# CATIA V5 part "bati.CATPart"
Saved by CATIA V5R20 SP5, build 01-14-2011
Part number: bati
Publications: "longueur bati", "epaisseur", "rayontrou"
Bounding box of the stored display mesh (mm): x -125 to 0, y 0 to 2100.481, z 0 to 1204.58
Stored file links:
  F:\iao fini\bati.CATPart
  F:\iao fini\iao-finipbgliss.CATProduct
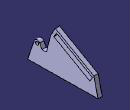
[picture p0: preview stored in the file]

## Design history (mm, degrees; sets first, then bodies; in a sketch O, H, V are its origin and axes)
Parameters
  `longueur bati` = 1 mm
  epaisseur = 125 mm
  rayontrou = 50 mm
Set1
  Plane1 "plan profil": linked copy from another document
  Point1: linked copy from another document
  Line1: linked copy from another document
  Point2: linked copy from another document
Body1 (main body)
  Sketch1 on Plane1, origin (0, 0, 0), H (0, 1, 0), V (0, 0, 1)
    line L1 (681.9123, 951.1125) -> (557.3138, 463.899)
    line L2 (681.9123, 951.1125) -> (825.4943, 1204.5798)
    line L3 (825.4943, 1204.5798) -> (1975.5785, 553.09)
    line L4 (1975.5785, 553.09) -> (2100.4814, 29.6002)
    line L5 (2100.4814, 29.6002) -> (0, 0)
    line L6 (557.3138, 463.899) -> (426.1909, 462.0512)
    arc A1 centre (280, 550) radius 90 from (360.0975, 591.0413) to (194.6984, 578.699) ccw
    point P7 (280, 550)
    reference projected point E1 (280, 550) from Point1
    line L7 (0, 0) -> (194.6984, 578.699)
    point P8 (0, 0)
    line L8 (360.0975, 591.0413) -> (426.1909, 462.0512)
    reference projected line E2 (2799.5367, -86.0537) -> (25.6737, 1485.2604) from Line1
    line L9 (856.3954, 1100.8777) -> (782.4628, 970.3635)
    line L10 (782.4628, 970.3635) -> (1857.0302, 361.6518)
    line L11 (1857.0302, 361.6518) -> (1930.9628, 492.1661)
    line L12 (1930.9628, 492.1661) -> (856.3954, 1100.8777)
    reference projected line E3 (2799.5367, -86.0537) -> (25.6737, 1485.2604) from Line1
    reference projected point E4 (280, 550) from Point1
    reference projected line E5 (2799.5367, -86.0537) -> (25.6737, 1485.2604) from Line1
    reference projected line E6 (2799.5367, -86.0537) -> (25.6737, 1485.2604) from Line1
    reference projected point E7 (280, 550) from Point1
    reference projected point E8 (280, 550) from Point1
    reference projected point E9 (280, 550) from Point1
    reference projected point E10 (280, 550) from Point1
    reference projected line E11 (2799.5367, -86.0537) -> (25.6737, 1485.2604) from Line1
    reference projected line E12 (2799.5367, -86.0537) -> (25.6737, 1485.2604) from Line1
    reference projected line E13 (2799.5367, -86.0537) -> (25.6737, 1485.2604) from Line1
    distance A1 E4 = 90 {= `longueur bati` *90}
    distance E5 L3 = 150 {= `longueur bati` *150}
    distance E6 L12 = 75 {= `longueur bati` *75}
    distance L9 E7 = 230 {= `longueur bati` *230}
    distance L11 L9 = 1235 {= `longueur bati` *1235}
    distance E8 L2 = 152 {= `longueur bati` *152}
    distance L6 L5 = 456 {= `longueur bati` *456}
    distance L8 O = 590 {= `longueur bati` *590}
    distance L4 O = 2050 {= `longueur bati` *2050}
    distance E9 L4 = 1650 {= `longueur bati` *1650}
    distance E10 L1 = 290 {= `longueur bati` *290}
    distance O L1 = 425 {= `longueur bati` *425}
    tangency: A1 L6, L7 A1, L8 A1
    coincidence: P7 E1, P8 L5, P8 H, O P8
    perpendicularity: L2 L3, L10 L9, L12 L11, L10 L11, L9 L12
    parallelism: E2 L3, L9 L2, L12 L10, E11 L12, E12 L10, E13 L12
    symmetry: L12 L10 E3
  Pad1: profile Sketch1, direction (-1, 0, 0), length 125 {= epaisseur}
  Sketch2 on Plane1, origin (0, 0, 0), H (0, 1, 0), V (0, 0, 1)
    circle A1 centre (1500.1993, 649.9838) radius 25
    point P1 (1500.1993, 649.9838)
    reference projected point E1 (1500.1993, 649.9838) from Point2
    circle A2 centre (280, 550) radius 50
    point P2 (280, 550)
    reference projected point E2 (280, 550) from Point1
    radius A1 = 25 {= 1/2*rayontrou}
    radius A2 = 50 {= rayontrou}
    coincidence: E1 P1, P2 E2
  Pocket1: profile Sketch2, direction (-1, 0, 0), length 125 {= epaisseur}
Relations
  Sketch1.distance(L8 O) = 590* (deactivated)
